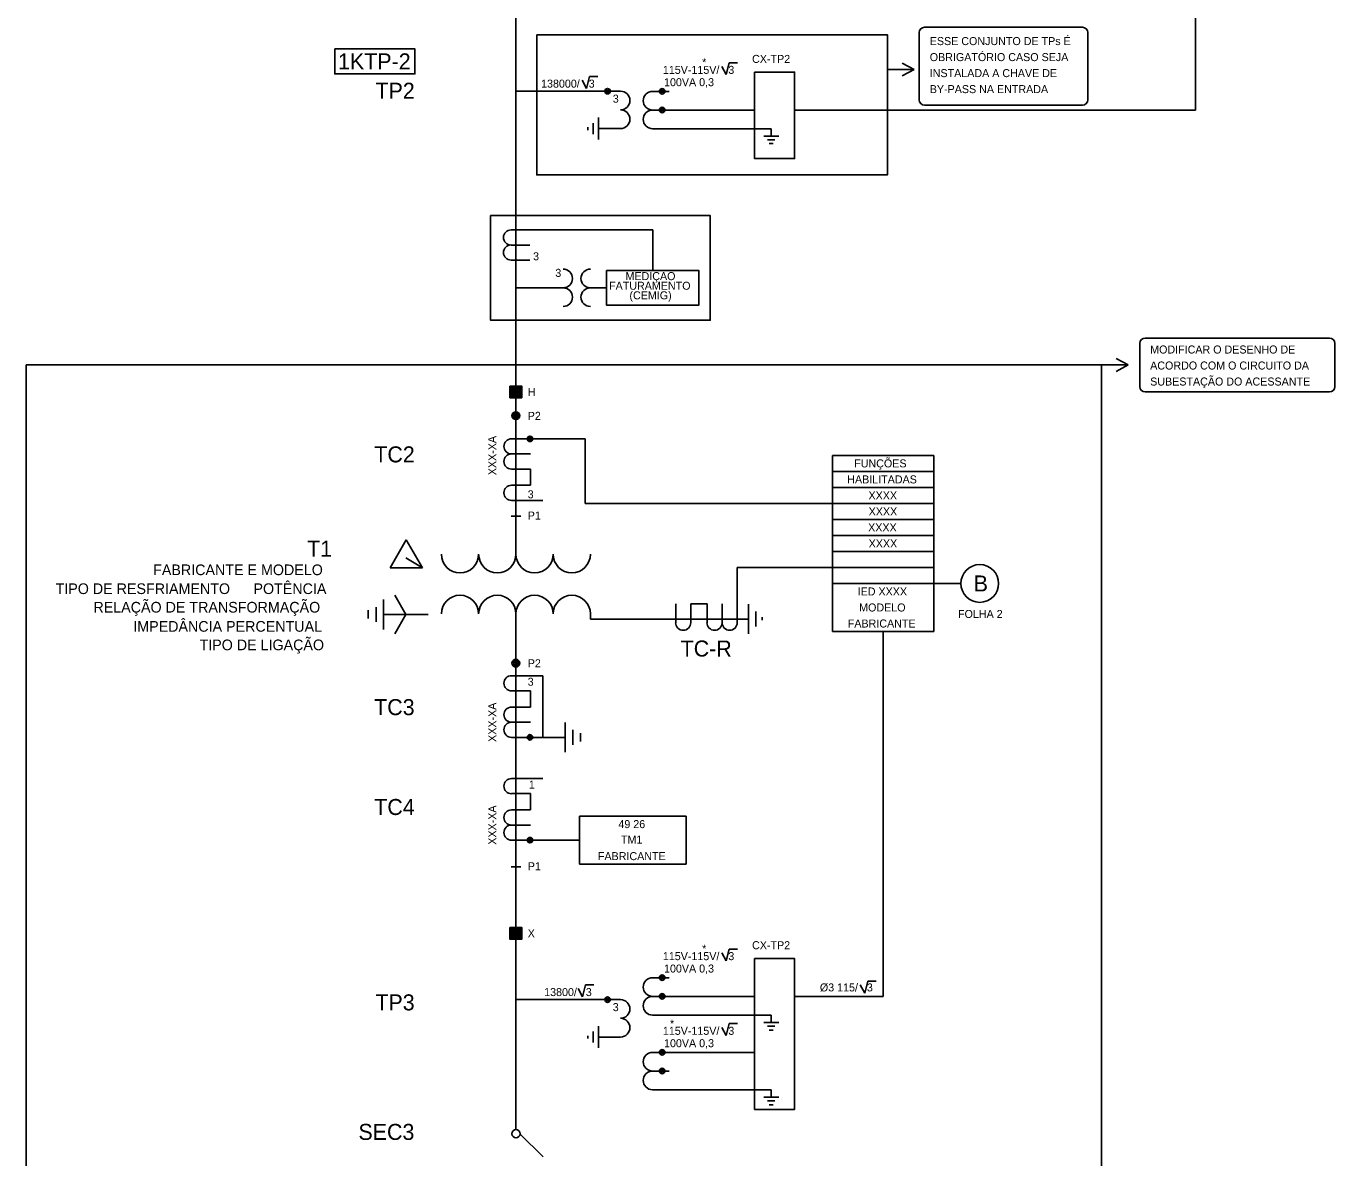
# Model space of a CAD drawing. Extents: x 563 to 1404, y 358 to 952.
# Drawn here: x 822.7 to 1067.9, y 525.8 to 737.8 of the extents above; entities that cross this region are included whole.
import ezdxf

# ---------------------------------------------------------------- set-up
doc = ezdxf.new("R2010")
doc.units = 0
doc.layers.add('New Level (0)', color=7, linetype='Continuous')

# ---------------------------------------------------------------- blocks, each defined once
blk = doc.blocks.new('_U3')
for p, q in [((-1.47, 0.42), (-0.62, -1.12)), ((-0.62, -1.12), (-0.07, 1.12)), ((-0.07, 1.12), (1.47, 1.12))]:
    blk.add_line(p, q)

msp = doc.modelspace()

# ---------------------------------------------------------------- linework, layer by layer
for p, q in [((914.46, 680.4), (914.46, 782.45)), ((914.46, 725.65), (934.06, 725.65)), ((940.06, 725.62), (943.17, 725.62)), ((940.06, 722.12), (959.19, 722.12)), ((966.67, 722.12), (1041.8, 722.12)), ((927.93, 718.89), (927.93, 718.35)), ((928.94, 717.63), (928.94, 719.68)), ((929.96, 720.7), (929.96, 716.6)), ((934.06, 718.65), (929.96, 718.65)), ((940.06, 718.62), (962.29, 718.62)), ((962.29, 718.62), (962.29, 717.22)), ((963.69, 717.22), (960.89, 717.22)), ((961.59, 716.52), (962.99, 716.52)), ((961.94, 715.82), (962.63, 715.82)), ((913.55, 699.66), (917.09, 699.66)), ((917.09, 699.66), (940.08, 699.66)), ((913.55, 696.83), (917.09, 696.83)), ((913.55, 694), (917.09, 694)), ((914.46, 688.81), (923.3, 688.81)), ((928.4, 688.81), (931.4, 688.81)), ((914.46, 638.47), (914.46, 680.4)), ((913.34, 668.26), (915.49, 670.41)), ((913.34, 668.44), (915.32, 670.41)), ((913.34, 668.61), (915.14, 670.41)), ((913.34, 668.79), (914.96, 670.41)), ((913.34, 668.97), (914.79, 670.41)), ((913.34, 669.14), (914.61, 670.41)), ((913.34, 669.32), (914.43, 670.41)), ((913.34, 669.5), (914.26, 670.41)), ((913.34, 669.67), (914.08, 670.41)), ((913.34, 669.85), (913.9, 670.41)), ((913.34, 670.03), (913.73, 670.41)), ((913.34, 670.2), (913.55, 670.41)), ((913.34, 670.38), (913.37, 670.41)), ((913.46, 668.2), (915.55, 670.29)), ((913.64, 668.2), (915.55, 670.12)), ((913.81, 668.2), (915.55, 669.94)), ((913.99, 668.2), (915.55, 669.76)), ((914.17, 668.2), (915.55, 669.59)), ((914.34, 668.2), (915.55, 669.41)), ((914.52, 668.2), (915.55, 669.23)), ((914.7, 668.2), (915.55, 669.06)), ((914.87, 668.2), (915.55, 668.88)), ((915.05, 668.2), (915.55, 668.7)), ((915.23, 668.2), (915.55, 668.53)), ((915.4, 668.2), (915.55, 668.35)), ((913.64, 660.51), (927.45, 660.51)), ((927.45, 648.41), (927.45, 660.51)), ((913.64, 657.68), (917.18, 657.68)), ((973.77, 657.41), (973.77, 624.41)), ((992.76, 657.41), (973.77, 657.41)), ((992.76, 657.41), (992.76, 624.41)), ((913.64, 654.85), (917.18, 654.85)), ((917.18, 651.8), (917.18, 654.85)), ((992.76, 654.41), (973.77, 654.41)), ((913.64, 651.8), (917.18, 651.8)), ((992.76, 651.41), (973.77, 651.41)), ((913.64, 648.97), (919.51, 648.97)), ((927.45, 648.41), (974.38, 648.41)), ((992.76, 648.41), (973.77, 648.41)), ((992.76, 645.41), (973.77, 645.41)), ((890.88, 636.33), (893.91, 641.57)), ((893.91, 641.57), (896.93, 636.33)), ((992.76, 642.41), (973.77, 642.41)), ((896.93, 636.33), (893.84, 638.21)), ((992.76, 639.41), (973.77, 639.41)), ((992.76, 639.41), (973.77, 639.41)), ((896.93, 636.33), (890.88, 636.33)), ((955.93, 626.06), (955.93, 636.41)), ((955.93, 636.41), (973.77, 636.41)), ((992.76, 636.41), (973.77, 636.41)), ((997.83, 633.41), (973.77, 633.41)), ((889.65, 624.8), (889.65, 630.39)), ((893.84, 627.6), (891.75, 631.23)), ((886.77, 626.82), (886.77, 628.38)), ((888.25, 628.99), (888.25, 626.2)), ((944.39, 626.06), (944.39, 629.59)), ((947.22, 629.59), (950.27, 629.59)), ((947.22, 626.06), (947.22, 629.59)), ((950.27, 626.06), (950.27, 629.59)), ((953.1, 626.06), (953.1, 629.59)), ((958.05, 629.54), (958.05, 623.96)), ((959.44, 625.36), (959.44, 628.15)), ((898.03, 627.6), (889.65, 627.6)), ((893.84, 627.6), (891.75, 623.97)), ((928.42, 627.71), (928.42, 626.75)), ((928.42, 626.75), (958.05, 626.75)), ((960.61, 627.09), (960.61, 626.56)), ((992.76, 624.41), (973.77, 624.41)), ((983.27, 556.04), (983.27, 624.41)), ((913.64, 616.12), (919.51, 616.12)), ((913.64, 613.29), (917.18, 613.29)), ((917.18, 613.29), (917.18, 610.24)), ((913.64, 610.24), (917.18, 610.24)), ((913.64, 607.41), (917.18, 607.41)), ((923.7, 601.79), (923.7, 607.37)), ((925.09, 605.98), (925.09, 603.19)), ((913.64, 604.58), (917.18, 604.58)), ((917.18, 604.58), (923.7, 604.58)), ((926.57, 603.8), (926.57, 605.36)), ((913.64, 596.86), (919.51, 596.86)), ((913.64, 594.03), (917.18, 594.03)), ((917.18, 594.03), (917.18, 590.98)), ((913.64, 590.98), (917.18, 590.98)), ((926.38, 589.82), (926.38, 580.82)), ((926.38, 589.82), (946.37, 589.82)), ((946.37, 589.82), (946.37, 580.82)), ((913.64, 588.15), (917.18, 588.15)), ((913.64, 585.32), (926.38, 585.32)), ((913.64, 585.32), (917.18, 585.32)), ((926.38, 580.82), (946.37, 580.82)), ((913.34, 566.8), (915.49, 568.96)), ((913.34, 566.98), (915.32, 568.96)), ((913.34, 567.16), (915.14, 568.96)), ((913.34, 567.33), (914.96, 568.96)), ((913.34, 567.51), (914.79, 568.96)), ((913.34, 567.69), (914.61, 568.96)), ((913.34, 567.86), (914.43, 568.96)), ((913.34, 568.04), (914.26, 568.96)), ((913.34, 568.22), (914.08, 568.96)), ((913.34, 568.39), (913.9, 568.96)), ((913.34, 568.57), (913.73, 568.96)), ((913.34, 568.75), (913.55, 568.96)), ((913.34, 568.92), (913.37, 568.96)), ((913.46, 566.74), (915.55, 568.84)), ((913.64, 566.74), (915.55, 568.66)), ((913.81, 566.74), (915.55, 568.48)), ((913.99, 566.74), (915.55, 568.31)), ((914.17, 566.74), (915.55, 568.13)), ((914.34, 566.74), (915.55, 567.95)), ((914.52, 566.74), (915.55, 567.78)), ((914.7, 566.74), (915.55, 567.6)), ((914.87, 566.74), (915.55, 567.42)), ((915.05, 566.74), (915.55, 567.25)), ((915.23, 566.74), (915.55, 567.07)), ((915.4, 566.74), (915.55, 566.89)), ((940.06, 559.54), (943.17, 559.54)), ((914.46, 555.43), (934.06, 555.43)), ((940.06, 556.04), (959.19, 556.04)), ((966.67, 556.04), (983.27, 556.04)), ((940.06, 552.54), (962.29, 552.54)), ((962.29, 552.54), (962.29, 551.14)), ((928.94, 547.41), (928.94, 549.46)), ((929.96, 550.48), (929.96, 546.38)), ((963.69, 551.14), (960.89, 551.14)), ((961.59, 550.44), (962.99, 550.44)), ((961.94, 549.74), (962.63, 549.74)), ((927.93, 548.67), (927.93, 548.13)), ((934.06, 548.43), (929.96, 548.43)), ((959.19, 545.55), (940.06, 545.55)), ((940.06, 542.05), (943.17, 542.05)), ((940.06, 538.55), (962.29, 538.55)), ((963.69, 537.15), (960.89, 537.15)), ((962.29, 538.55), (962.29, 537.15)), ((961.59, 536.45), (962.99, 536.45)), ((961.94, 535.75), (962.63, 535.75)), ((919.56, 525.96), (915.22, 530.3))]:
    msp.add_line(p, q)
for points in [[(913.34, 670.41), (915.55, 670.41), (915.55, 668.2), (913.34, 668.2)], [(913.34, 568.96), (915.55, 568.96), (915.55, 566.74), (913.34, 566.74)]]:
    msp.add_lwpolyline(points, close=True)
for centre, radius in [((931.62, 725.65), 0.511), ((931.62, 725.65), 0.288), ((941.86, 725.62), 0.511), ((941.86, 725.62), 0.288), ((941.86, 722.12), 0.511), ((941.86, 722.12), 0.288), ((914.45, 664.85), 0.729), ((914.46, 664.85), 0.511), ((914.46, 664.85), 0.288), ((917.09, 660.51), 0.511), ((917.09, 660.51), 0.288), ((914.45, 618.49), 0.729), ((914.46, 618.48), 0.511), ((914.46, 618.48), 0.288), ((917.09, 604.58), 0.511), ((917.09, 604.58), 0.288), ((917.09, 585.32), 0.511), ((917.09, 585.32), 0.288), ((941.86, 559.54), 0.511), ((941.86, 559.54), 0.288), ((931.62, 555.43), 0.511), ((931.62, 555.43), 0.288), ((941.86, 556.04), 0.511), ((941.86, 556.04), 0.288), ((941.86, 545.55), 0.511), ((941.86, 545.55), 0.288), ((941.86, 542.05), 0.511), ((941.86, 542.05), 0.288), ((914.46, 530.3), 0.768)]:
    msp.add_circle(centre, radius)
for centre, radius, start, end in [((934.06, 723.9), 1.75, 270, 90), ((940.06, 723.87), 1.75, 90, 270), ((934.06, 720.4), 1.75, 270, 90), ((940.06, 720.37), 1.75, 90, 270), ((913.55, 698.25), 1.42, 90, 270), ((913.55, 695.42), 1.42, 90, 270), ((923.3, 690.56), 1.75, 270, 90), ((928.4, 690.56), 1.75, 90, 270), ((923.3, 687.06), 1.75, 270, 90), ((928.4, 687.06), 1.75, 90, 270), ((913.64, 659.1), 1.42, 90, 270), ((913.64, 656.27), 1.42, 90, 270), ((913.64, 650.39), 1.42, 90, 270), ((903.98, 638.89), 3.49, 180, 0), ((910.96, 638.89), 3.49, 180, 0), ((917.95, 638.89), 3.49, 180, 0), ((924.93, 638.89), 3.49, 180, 0), ((903.98, 627.71), 3.49, 0, 180), ((910.96, 627.71), 3.49, 0, 180), ((917.95, 627.71), 3.49, 0, 180), ((924.93, 627.71), 3.49, 0, 180), ((945.8, 626.06), 1.42, 180, 0), ((951.68, 626.06), 1.42, 180, 0), ((954.51, 626.06), 1.42, 180, 0), ((913.64, 614.71), 1.42, 90, 270), ((913.64, 608.83), 1.42, 90, 270), ((913.64, 606), 1.42, 90, 270), ((913.64, 595.44), 1.42, 90, 270), ((913.64, 589.56), 1.42, 90, 270), ((913.64, 586.73), 1.42, 90, 270), ((940.06, 557.79), 1.75, 90, 270), ((934.06, 553.68), 1.75, 270, 90), ((940.06, 554.29), 1.75, 90, 270), ((934.06, 550.18), 1.75, 270, 90), ((940.06, 543.8), 1.75, 90, 270), ((940.06, 540.3), 1.75, 90, 270)]:
    msp.add_arc(centre, radius, start, end)
at = {"layer": 'New Level (0)'}
for p, q in [((1041.8, 774.47), (1041.8, 722.12)), ((990.01, 724.04), (990.01, 736.63)), ((991.01, 737.63), (1020.62, 737.63)), ((1021.62, 736.63), (1021.62, 724.04)), ((989.11, 729.71), (986.82, 730.91)), ((984.08, 729.71), (989.11, 729.71)), ((989.11, 729.71), (986.82, 728.5)), ((1020.62, 723.04), (991.01, 723.04)), ((940.08, 692.05), (940.08, 699.66)), ((1032.36, 679.4), (1039.71, 679.4)), ((1039.71, 679.4), (1066.9, 679.4)), ((1031.36, 670.29), (1031.36, 678.4)), ((1067.9, 678.4), (1067.9, 670.29)), ((1024.17, 674.35), (1029.2, 674.35)), ((1029.2, 674.35), (1026.9, 675.55)), ((1029.2, 674.35), (1026.9, 673.14)), ((1066.9, 669.29), (1032.36, 669.29)), ((913.56, 646.01), (915.36, 646.01)), ((914.46, 627.71), (914.46, 531.07)), ((919.51, 604.58), (919.51, 616.12)), ((913.56, 580.29), (915.36, 580.29))]:
    msp.add_line(p, q, dxfattribs=at)
for points in [[(918.36, 736.22), (984.08, 736.22), (984.08, 709.96), (918.36, 709.96)], [(880.5, 733.56), (895.52, 733.56), (895.52, 728.88), (880.5, 728.88)], [(959.19, 729.22), (966.67, 729.22), (966.67, 713.01), (959.19, 713.01)], [(909.72, 702.33), (950.88, 702.33), (950.88, 682.72), (909.72, 682.72)], [(931.4, 692.05), (948.75, 692.05), (948.75, 685.58), (931.4, 685.58)], [(822.69, 674.35), (1024.17, 674.35), (1024.17, 424.93), (822.69, 424.93)], [(959.19, 563.14), (966.67, 563.14), (966.67, 534.85), (959.19, 534.85)]]:
    msp.add_lwpolyline(points, close=True, dxfattribs=at)
msp.add_circle((1001.37, 633.41), 3.54, dxfattribs=at)
for centre, start, end in [((991.01, 736.63), 90, 180), ((1020.62, 736.63), 0, 90), ((991.01, 724.04), 180, 270), ((1020.62, 724.04), 270, 0), ((1032.36, 678.4), 90, 180), ((1066.9, 678.4), 0, 90), ((1032.36, 670.29), 180, 270), ((1066.9, 670.29), 270, 0)]:
    msp.add_arc(centre, 1, start, end, dxfattribs=at)

# ---------------------------------------------------------------- block references
for p in [(954.49, 729.87), (928.32, 727.29), (954.49, 563.8), (927.56, 557.07), (980.46, 557.77), (954.49, 549.81)]:
    msp.add_blockref('_U3', p)

# ---------------------------------------------------------------- texts
for s, height, p in [('ESSE CONJUNTO DE TPs É ', 1.5, (992, 734.29)), ('1KTP-2', 3, (881.13, 729.74)), ('*', 1.5, (949.35, 730.33)), ('CX-TP2', 1.5, (958.71, 730.95)), ('OBRIGATÓRIO CASO SEJA ', 1.5, (992, 731.29)), ('115V-115V/   3', 1.5, (941.99, 728.9)), ('INSTALADA A CHAVE DE ', 1.5, (992, 728.29)), ('TP2', 3, (888.14, 724.24)), ('138000/   3', 1.5, (919.17, 726.32)), ('100VA 0,3', 1.5, (942.21, 726.59)), ('BY-PASS NA ENTRADA', 1.5, (992, 725.29)), ('3', 1.5, (932.6, 723.5)), ('3', 1.5, (917.67, 693.97)), ('3', 1.5, (921.84, 690.86)), ('MEDIÇÃO', 1.5, (934.99, 690.25)), ('FATURAMENTO', 1.5, (931.91, 688.45)), ('(CEMIG)', 1.5, (935.73, 686.65)), ('MODIFICAR O DESENHO DE ', 1.5, (1033.3, 676.5)), ('ACORDO COM O CIRCUITO DA ', 1.5, (1033.3, 673.5)), ('SUBESTAÇÃO DO ACESSANTE', 1.5, (1033.3, 670.5)), ('H', 1.5, (916.67, 668.56)), ('P2', 1.5, (916.67, 664.07)), ('TC2', 3, (887.92, 656.1)), ('FUNÇÕES ', 1.5, (977.84, 655.16)), ('HABILITADAS', 1.5, (976.54, 652.16)), ('3', 1.5, (916.66, 649.37)), ('XXXX', 1.5, (980.52, 649.16)), ('XXXX', 1.5, (980.55, 646.16)), ('P1', 1.5, (916.67, 645.39)), ('XXXX', 1.5, (980.45, 643.16)), ('T1', 3, (875.33, 638.44)), ('XXXX', 1.5, (980.55, 640.16)), ('FABRICANTE E MODELO', 2, (846.48, 634.97)), ('TIPO DE RESFRIAMENTO ', 2, (828.2, 631.43)), ('POTÊNCIA', 2, (865.28, 631.43)), ('IED XXXX', 1.5, (978.49, 631.16)), ('B', 3, (1000.24, 631.91)), ('RELAÇÃO DE TRANSFORMAÇÃO', 2, (835.29, 627.96)), ('MODELO', 1.5, (978.77, 628.16)), ('FOLHA 2', 1.5, (997.3, 626.95)), ('IMPEDÂNCIA PERCENTUAL', 2, (842.76, 624.37)), ('FABRICANTE', 1.5, (976.64, 625.16)), ('TIPO DE LIGAÇÃO', 2, (855.17, 620.9)), ('TC-R', 3, (945.32, 619.72)), ('P2', 1.5, (916.67, 617.71)), ('3', 1.5, (916.66, 614.25)), ('TC3', 3, (887.89, 608.74)), ('1', 1.5, (916.88, 594.97)), ('TC4', 3, (887.91, 590.03)), ('49 26', 1.5, (933.66, 587.57)), ('TM1', 1.5, (934.14, 584.68)), ('P1', 1.5, (916.67, 579.67)), ('FABRICANTE', 1.5, (929.82, 581.57)), ('X', 1.5, (916.67, 567.1)), ('115V-115V/   3', 1.5, (941.99, 562.83)), ('*', 1.5, (949.35, 564.25)), ('CX-TP2', 1.5, (958.71, 564.88)), ('100VA 0,3', 1.5, (942.21, 560.51)), ('13800/   3', 1.5, (919.75, 556.1)), ('Ø3 115/   3', 1.5, (971.41, 556.97)), ('TP3', 3, (888.12, 553.42)), ('3', 1.5, (932.6, 553.28)), ('115V-115V/   3', 1.5, (941.99, 548.84)), ('*', 1.5, (943.32, 550.2)), ('100VA 0,3', 1.5, (942.21, 546.52)), ('SEC3', 3, (884.95, 529.15))]:
    msp.add_text(s, height=height).set_placement(p)
for p in [(910.77, 653.7), (910.77, 603.72), (910.77, 584.46)]:
    msp.add_text('XXX-XA', height=1.5, rotation=90).set_placement(p)

doc.saveas('drawing.dxf')
